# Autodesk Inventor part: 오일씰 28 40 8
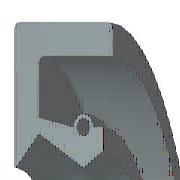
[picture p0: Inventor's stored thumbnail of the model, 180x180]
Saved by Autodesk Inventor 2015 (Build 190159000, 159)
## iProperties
IsCustomPart: 1
Created: 2012-02
Part Number: 오일씰 28 40 8
Material: 고무
Description: Oil-seal
Document SubType Name: Modeling
Standard: KS B 2804
Designer: mduedu
Standards Organization: KS
Language: en-US
Size Designation: D - 28 40 8
Categories: <MemberInstance><Categories><Category DisplayName="Shaft Parts" InternalName="7f7aeb1f-a693-4053-b835-cee3144e0d98" Mnemonic="SHFT"><Category DisplayName="Seali
Density: 0.93 g/cm^3
Mass: 2.83894 g
Surface Area: 40.7521 cm^2
Volume: 3.05262 cm^3
Appearance: 고무 - 검은색 - 버전 1.1
Author: mduedu
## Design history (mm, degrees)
sketch "Sketch1"
  geometry: L1 (0, 20)-(8, 20); L2 (8, 18.25)-(1.75, 18.25); L3 (1.75, 15.75)-(4.9, 14); L4 (4.9, 14)-(0, 14); L5 (0, 0)-(9.586, 0) reference; L6 (4.9, 14)-(6.3, 14.875); L7 (0, 18)-(0, -3) reference; L8 (-1.941, 0)-(11.507, 0) reference; L9 (4.2, 16.1)-(1.75, 16.71); L10 (1.75, 16.71)-(1.75, 18.25); L11 (0, 20)-(0, 14.088); L12 (4.9, 14)-(0, 14); L13 (1.75, 15.75)-(0.152, 14.028); L14 (8, 20)-(8, 18.25); L15 (5.6, 16.1)-(6.3, 16.1); L16 (6.3, 16.1)-(6.3, 14.875); C1 r 0.455 at (4.9, 16.1); A1 r 0.7 centre (4.9, 16.1) between (5.6, 16.1) and (4.2, 16.1); A2 r 0.088 centre (0.087, 14.088) between (0, 14.088) and (0.152, 14.028); 1 further point
  constraints: 28 end point, 5 horizontal alignment, 5 point on line, 4 point on circle, 4 vertical alignment, 3 centre point, 3 tangent, 2 collinear, 2 horizontal, 2 perpendicular, 1 coincident, 1 parallel
  dimensions: "d0" = 40 diameter of L1 L5 (= SD2); "d1" = 1.75 distance of L1.end L2.start (= SD); "d2" = 0.91 diameter of C1 (= SPDI); "d3" = 1.4 diameter of A1 (= SPDA); "d4" = 28 diameter of L3.end L5 (= NND); "d5" = 31.5 diameter of L3.start L5 (= TKDM); "d7" = 33.42 diameter of L9.end L5 (= TKDM + 0.24 x SWDT); "d8" = 1.75 distance between parallel lines of L11 L10 (= SD); "d9" = 4.9 distance from line of L11 C1.centre (= SPDST); "d10" = 32.2 diameter of C1.centre L5 (= HLDM); "d11" = 0.0875 radius of A2 (= 0.25 x LAB); "d12" = 6.3 distance between parallel lines of L11 L16 (= SDI); "d13" = 29.75 diameter of L6.end L5 (= ABDM); "d14" = 8 distance from line of L11 L1.end (= SWDT)
revolve "Body" stored, may be unused: angle "d17" = 90 deg
revolve "Spring1" stored, may be unused: angle "d18" = 90 deg
fillet "Fillet1" dims "d6" = 0.4 (= RR)
body "Solid1"
other parameters: "SD2" = 40 [user parameter; used in 1 equation term], "SWDT" = 8 [user parameter; used in 2 equation terms], "RR" = 0.4 [user parameter; used in 1 equation term], "SD" = 1.75 [user parameter; used in 2 equation terms], "NND" = 28 [user parameter; used in 1 equation term], "SPDA" = 1.4 [user parameter; used in 1 equation term], "SPDI" = 0.91 [user parameter; used in 1 equation term], "TKDM" = 31.5 [user parameter; used in 2 equation terms], "HLDM" = 32.2 [user parameter; used in 1 equation term], "ABDM" = 29.75 [user parameter; used in 1 equation term], "SDI" = 6.3 [user parameter; used in 1 equation term], "SPDST" = 4.9 [user parameter; used in 1 equation term], "LAB" = 0.35 [user parameter; used in 1 equation term], "d15" = 0, "d16" = 0, "d19" = 0
